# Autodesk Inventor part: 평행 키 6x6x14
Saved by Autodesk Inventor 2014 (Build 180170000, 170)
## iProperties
Created: 2025-09
Part Number: 평행 키 6x6x14
Material: 일반
Document SubType Name: Modeling
Designer: dg
Density: 1 g/cm^3
Appearance: 기본값
Author: dg
Author: jhkim
Description: 키 및 해당 키홈
Creation Date: 2025-09-02
Sending System: Autodesk Inventor 2026
Preprocessor: ST-DEVELOPER v20.1
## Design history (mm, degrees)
node "평행 키 6x6x141"
body "Solid1"
node "기준1"
